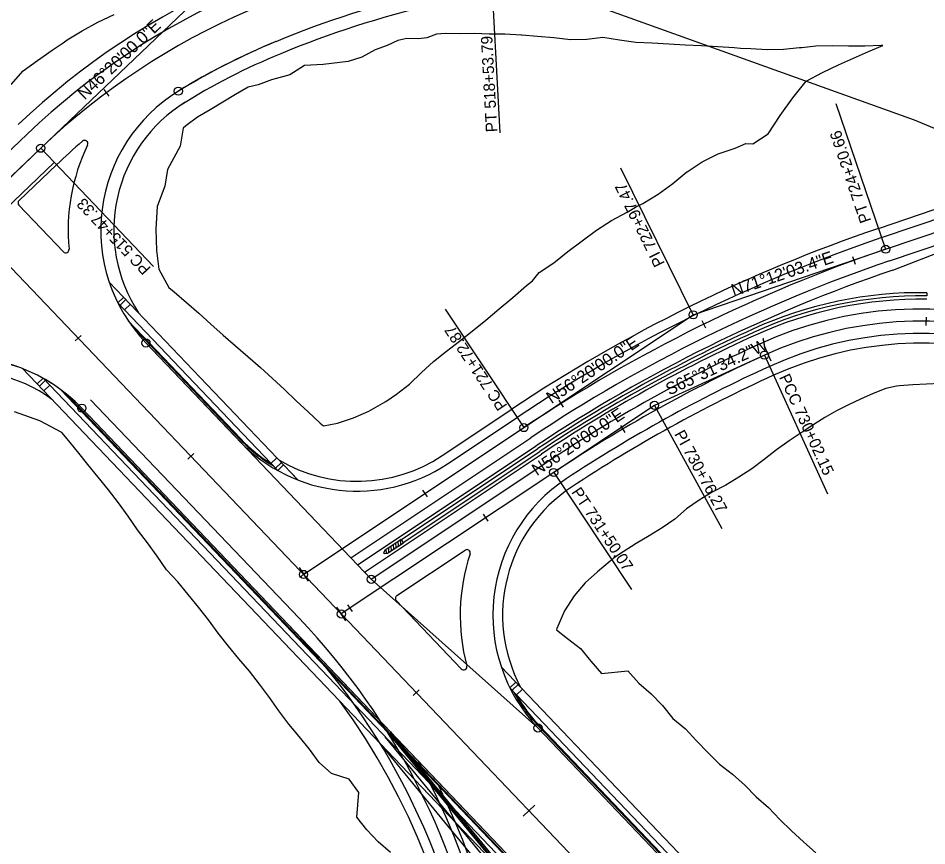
# Model space of a CAD drawing. Extents: x 1300404 to 1323571, y 234004 to 252077.
# Drawn here: x 1310184 to 1310741, y 241283 to 241789 of the extents above; entities that cross this region are included whole.
import ezdxf

# ---------------------------------------------------------------- set-up
doc = ezdxf.new("R2010")
doc.units = 0
for name, color, linetype in [('R_Attenuator', 7, 'Continuous'), ('R_Flooplain', 7, 'Continuous'), ('R_Future', 7, 'Continuous'), ('R_Lane Edge', 7, 'Continuous'), ('R_Shoulder', 7, 'Continuous'), ('R_Sidewalk Edge', 7, 'Continuous'), ('S_CONTOUR_ANNOT', 7, 'Continuous'), ('S_CONTOUR_MINOR', 7, 'Continuous'), ('S_CURB_ANNOT', 7, 'Continuous'), ('S_EDGE_PAVEMENT_ANNOT', 7, 'Continuous'), ('S_ELECTRIC_UTILITIES_ANNOT', 7, 'Continuous'), ('S_LANDSCAPING_ANNOT', 7, 'Continuous'), ('S_POOL', 7, 'Continuous'), ('S_SANITARY_SEWER_ANNOT', 7, 'Continuous'), ('S_SIGN', 7, 'Continuous'), ('S_TREE_ANNOT', 7, 'Continuous'), ('S_UTL_PT_SYM', 7, 'Continuous')]:
    doc.layers.add(name, color=color, linetype=linetype)

msp = doc.modelspace()

# ---------------------------------------------------------------- linework, layer by layer
at = {"layer": 'R_Attenuator'}
for p, q in [((1310412.72, 241463.26), (1310412.54, 241466.14)), ((1310414.16, 241464.22), (1310413.98, 241467.1)), ((1310415.6, 241465.18), (1310415.42, 241468.06)), ((1310417.05, 241466.14), (1310416.86, 241469.03)), ((1310418.49, 241467.1), (1310418.3, 241469.99)), ((1310420.1, 241468.18), (1310418.71, 241470.26)), ((1310419.93, 241468.06), (1310419.9, 241468.47)), ((1310409.02, 241463.8), (1310407.99, 241461.97)), ((1310408.33, 241461.48), (1310408.26, 241462.46)), ((1310408.32, 241461.48), (1310410.41, 241461.72)), ((1310409.82, 241461.65), (1310409.65, 241464.22)), ((1310411.28, 241462.3), (1310411.09, 241465.18))]:
    msp.add_line(p, q, dxfattribs=at)
for points in [[(1310409.02, 241463.8), (1310418.71, 241470.26)], [(1310410.41, 241461.72), (1310420.1, 241468.18)]]:
    msp.add_lwpolyline(points, dxfattribs=at)
msp.add_arc((1310408.49, 241461.95), 0.5, 176.9567, 249.5211, dxfattribs=at)
at = {"layer": 'R_Flooplain'}
msp.add_lwpolyline([(1308850.44, 242983.42), (1308921.9, 242863.68), (1309009.78, 242685.04), (1309044.07, 242596.21), (1309055.9, 242542.38), (1309352.07, 242367.77), (1309503.16, 242292.41), (1309669.46, 242230.8), (1309815.49, 242150.85), (1309936.66, 242057.64), (1310419.39, 241839.75), (1310733.16, 241727.16), (1311043.67, 241597.79), (1311103.17, 241577.86), (1311152.77, 241553.58), (1311178, 241525.7), (1311328.48, 241486.66), (1311553.07, 241380.98), (1311870.34, 241289.99), (1312137.52, 241213.62), (1312460.11, 241035.25)], dxfattribs=at)
at = {"layer": 'R_Future'}
for p, q in [((1310228.47, 241555.74), (1310356.22, 241421.9)), ((1310504.53, 241233.21), (1310408.91, 241349.31)), ((1310506.77, 241235.21), (1310411.16, 241351.31)), ((1310411.52, 241351.65), (1310507.13, 241235.55)), ((1310412.25, 241352.34), (1310507.86, 241236.24)), ((1310500.78, 241229.89), (1310405.17, 241345.99))]:
    msp.add_line(p, q, dxfattribs=at)
for radius, end in [(432.42, 43.6667), (424.92, 43.6667), (418.92, 36.2551), (439.92, 28.6616), (443.92, 26.1864)]:
    msp.add_arc((1310043.42, 241123.33), radius, 336.8233, end, dxfattribs=at)
at = {"layer": 'R_Lane Edge'}
for p, q in [((1310713.17, 241655.01), (1311678.48, 241983.61)), ((1310718.01, 241640.81), (1311683.31, 241969.41)), ((1310165.2, 241695.16), (1310189.58, 241718.44)), ((1310184.6, 241677.73), (1310207.53, 241699.63)), ((1310184.53, 241674.91), (1310211.8, 241646.34)), ((1310262.33, 241590.5), (1310265.86, 241586.81)), ((1310265.86, 241586.81), (1310319.39, 241530.73)), ((1310223.05, 241550.56), (1310370.67, 241395.9)), ((1310447.16, 241516.54), (1310489.78, 241544.93)), ((1310387.84, 241459.01), (1310498.1, 241532.45)), ((1310400.46, 241445.79), (1310508.08, 241517.47)), ((1310416.06, 241435.75), (1310457.92, 241463.64)), ((1310400.46, 241445.79), (1310387.84, 241459.01)), ((1310415.72, 241432.7), (1310455.59, 241390.93)), ((1310370.67, 241395.9), (1310412.25, 241352.34)), ((1310502.57, 241354.75), (1310620.08, 241231.63)), ((1310412.25, 241352.34), (1311200.16, 240526.88))]:
    msp.add_line(p, q, dxfattribs=at)
for centre, radius, start, end in [((1310496.44, 241396.96), 444.42, 93.0604, 133.6667), ((1310574.96, 241212.44), 608.93, 93.92671, 112.49959), ((1310496.44, 241396.96), 408.42, 112.2282, 122.0916), ((1310334.67, 241659.55), 100, 121.6346, 223.6667), ((1310496.44, 241396.96), 418.42, 130.7161, 133.6667), ((1310334.67, 241659.55), 120, 154.2341, 185.5621), ((1310224.8, 241712.58), 2, 334.2336, 130.7163), ((1310185.98, 241676.29), 2, 133.6667, 223.6667), ((1311023.32, 240743.92), 962.43, 108.79905, 123.66667), ((1310213.25, 241647.72), 2, 223.6667, 5.562), ((1311023.32, 240743.92), 947.43, 108.79905, 123.66667), ((1310737.29, 241372.32), 239, 311.1667, 114.4738), ((1310737.29, 241372.32), 224, 311.1667, 114.4738), ((1311023.32, 240743.92), 929.43, 114.47385, 123.66667), ((1310150.71, 241481.51), 100, 43.6667, 147.1828), ((1311023.32, 240743.92), 914.43, 114.47385, 123.40686), ((1310391.73, 241599.77), 100, 223.6667, 303.6667), ((1310574.91, 241423.8), 100, 123.4069, 223.6667), ((1310574.91, 241423.8), 120, 161.7649, 194.9551), ((1310459.03, 241461.97), 2, 341.7649, 123.6667), ((1310417.17, 241434.08), 2, 123.6667, 223.6667), ((1310457.04, 241392.31), 2, 223.6667, 14.9551)]:
    msp.add_arc(centre, radius, start, end, dxfattribs=at)
at = {"layer": 'R_Shoulder'}
for p, q in [((1310711.24, 241660.69), (1311676.55, 241989.29)), ((1310719.94, 241635.13), (1310766.63, 241653.14)), ((1310443.84, 241521.54), (1310486.46, 241549.93)), ((1310392.05, 241454.6), (1310501.42, 241527.45)), ((1310396.26, 241450.2), (1310504.75, 241522.46))]:
    msp.add_line(p, q, dxfattribs=at)
for centre, radius, start, end in [((1310496.44, 241396.96), 452.42, 93.0604, 133.6667), ((1310574.96, 241212.44), 600.93, 93.93245, 112.5014), ((1310496.44, 241396.96), 400.42, 112.2255, 122.0916), ((1310334.67, 241659.55), 92, 121.6346, 213.3062), ((1311023.32, 240743.92), 968.43, 108.79905, 123.66667), ((1311023.32, 240743.92), 941.43, 108.79905, 123.66667), ((1310737.29, 241372.32), 245, 89.1568, 114.4738), ((1311023.32, 240743.92), 935.43, 114.47385, 123.66667), ((1310737.29, 241372.32), 218, 311.1667, 114.4738), ((1310150.71, 241481.51), 92, 54.0272, 147.1828), ((1311023.32, 240743.92), 908.43, 114.47385, 123.40686), ((1310391.73, 241599.77), 94, 239.3509, 303.6667), ((1310574.91, 241423.8), 94, 123.4069, 207.9824)]:
    msp.add_arc(centre, radius, start, end, dxfattribs=at)
at = {"layer": 'R_Sidewalk Edge'}
for p, q in [((1310239.83, 241627.83), (1310355.64, 241506.51)), ((1310248.73, 241618.52), (1310245.11, 241615.06)), ((1310250.11, 241617.07), (1310246.49, 241613.62)), ((1310245.11, 241615.06), (1310343.13, 241512.38)), ((1310252.87, 241614.18), (1310249.25, 241610.72)), ((1310186.8, 241574.77), (1310385.11, 241367.02)), ((1310199.31, 241568.91), (1310195.69, 241565.45)), ((1310200.69, 241567.46), (1310197.07, 241564.01)), ((1310199.31, 241568.91), (1310378.2, 241381.49)), ((1310203.45, 241564.57), (1310199.84, 241561.11)), ((1310338.98, 241516.72), (1310342.6, 241520.17)), ((1310341.75, 241513.82), (1310345.36, 241517.28)), ((1310343.13, 241512.38), (1310346.74, 241515.83)), ((1310349.8, 241512.62), (1310355.64, 241506.51)), ((1310480.07, 241392.08), (1310628.7, 241236.37)), ((1310488.96, 241382.76), (1310485.35, 241379.31)), ((1310378.2, 241381.49), (1310655.54, 241090.93)), ((1310485.35, 241379.31), (1310624.89, 241233.12)), ((1310490.34, 241381.32), (1310486.73, 241377.86)), ((1310493.11, 241378.42), (1310489.49, 241374.97)), ((1310385.11, 241367.02), (1310651.77, 241087.64))]:
    msp.add_line(p, q, dxfattribs=at)
at = {"layer": 'S_CONTOUR_ANNOT'}
for p, q in [((1310197.87, 241709.76), (1310313.6, 241820.22)), ((1310597.64, 241607.76), (1310715.59, 241647.91)), ((1310493.94, 241538.69), (1310597.64, 241607.76)), ((1310641.38, 241583.02), (1310573.92, 241552.31)), ((1310573.92, 241552.31), (1310512.23, 241511.22))]:
    msp.add_line(p, q, dxfattribs=at)
at = {"layer": 'S_CURB_ANNOT'}
for p, q in [((1310740.8, 241621.29), (1310740.77, 241619.29)), ((1310418.85, 241470.05), (1310502.53, 241525.79)), ((1310419.96, 241468.38), (1310503.64, 241524.12)), ((1310419.96, 241468.38), (1310418.85, 241470.05))]:
    msp.add_line(p, q, dxfattribs=at)
for centre, radius, start, end in [((1310737.29, 241372.32), 249, 89.1924, 114.4738), ((1310737.29, 241372.32), 247, 89.1924, 114.4738), ((1311023.32, 240743.92), 939.43, 114.47385, 123.66667), ((1311023.32, 240743.92), 937.43, 114.47385, 123.66667)]:
    msp.add_arc(centre, radius, start, end, dxfattribs=at)
at = {"layer": 'S_EDGE_PAVEMENT_ANNOT'}
for points in [[(1310473.35, 241828.76), (1310479.21, 241719.2)], [(1310685.18, 241737.26), (1310715.59, 241647.91)], [(1310197.87, 241709.76), (1310266.91, 241637.42)], [(1310597.64, 241607.76), (1310553.44, 241697.46)], [(1310445.66, 241611.18), (1310493.94, 241538.69)], [(1310641.38, 241583.02), (1310680.08, 241498.01)], [(1310573.92, 241552.31), (1310615.3, 241476.78)], [(1310512.23, 241511.22), (1310559.98, 241439.54)]]:
    msp.add_lwpolyline(points, dxfattribs=at)
at = {"layer": 'S_ELECTRIC_UTILITIES_ANNOT'}
for points in [[(1310179.85, 241748.72), (1310187.06, 241757.12), (1310195.99, 241763.55), (1310204.95, 241769.88), (1310211.59, 241774.39), (1310214, 241776.06), (1310223.37, 241781.73), (1310232.94, 241787.06), (1310242.9, 241791.7)], [(1310713.95, 241772.69), (1310712.9, 241772.72), (1310702.91, 241772.17), (1310692.89, 241772.34), (1310682.87, 241772.5), (1310672.87, 241772.24), (1310664.19, 241771.34), (1310662.91, 241771.2), (1310652.95, 241770.15), (1310642.95, 241769.98), (1310632.9, 241770.57), (1310626.66, 241770.88), (1310622.85, 241771.17), (1310612.8, 241771.81), (1310602.76, 241772.39), (1310592.71, 241772.96), (1310582.67, 241773.5), (1310572.63, 241774.03), (1310562.59, 241774.57), (1310552.5, 241775.86), (1310542.4, 241777.49), (1310532.44, 241776.42), (1310522.44, 241776.25), (1310512.36, 241777.44), (1310502.3, 241778.22), (1310492.71, 241778.96), (1310492.25, 241778.99), (1310482.2, 241779.56), (1310472.62, 241779.54), (1310463.69, 241779.93), (1310454.75, 241779.92), (1310445.76, 241779.98), (1310440.44, 241779.54), (1310434.56, 241777.46), (1310429.44, 241776.71), (1310422.15, 241776.9), (1310416.67, 241775.82), (1310410.07, 241772.76), (1310402.81, 241770.07), (1310394.62, 241765.57), (1310386.34, 241762.93), (1310370.98, 241760.99), (1310359.58, 241760.38), (1310350.48, 241754.73), (1310339.31, 241751.73), (1310331.18, 241748.58), (1310324.96, 241747.19), (1310317.19, 241742.58), (1310309.49, 241737.9), (1310301.79, 241733.25), (1310294.04, 241728.7), (1310286.73, 241723.46), (1310285.06, 241721.97), (1310283.4, 241710.95), (1310275.56, 241696.75), (1310273.87, 241686.49)], [(1310371.07, 241539.73), (1310379.67, 241541.4), (1310389.57, 241544.57), (1310398.83, 241548.72), (1310407.51, 241553.71), (1310409.3, 241554.76), (1310415.87, 241559.2), (1310423.84, 241565.27), (1310431.11, 241572.41), (1310438.62, 241579.17), (1310446.46, 241585.44), (1310454.39, 241591.57), (1310462.29, 241597.75), (1310470.64, 241604.43), (1310478.88, 241611.49), (1310487.25, 241618.41), (1310495.48, 241625.62), (1310499.13, 241628.6), (1310503.28, 241633.64), (1310512.36, 241639.56), (1310520.92, 241646.43), (1310529.71, 241652.96), (1310538.52, 241659.52), (1310547.68, 241665.47), (1310557.31, 241670.56), (1310562.39, 241673.58), (1310566.78, 241675.98), (1310576.13, 241681.68), (1310585.11, 241688.21), (1310593.88, 241695.29), (1310593.96, 241695.36), (1310603.1, 241701.51), (1310612.99, 241706.29), (1310623.39, 241709.9), (1310629.93, 241712.74), (1310634.18, 241712.5), (1310643.57, 241718.54), (1310650.98, 241729.81), (1310658.72, 241740.66), (1310666.89, 241750.78), (1310676.89, 241756.13), (1310686.82, 241760.86), (1310696.01, 241764.91), (1310705.2, 241768.92), (1310713.95, 241772.69)], [(1310273.87, 241686.49), (1310269.18, 241674.17), (1310268.49, 241660.3), (1310268.85, 241647.05), (1310270.15, 241635.61), (1310276.3, 241624.5), (1310279.63, 241621.91), (1310287.24, 241615.34), (1310294.73, 241608.67), (1310302.19, 241601.97), (1310309.72, 241595.33), (1310317.28, 241588.72), (1310324.88, 241582.15), (1310332.48, 241575.58), (1310339.88, 241568.83), (1310347.18, 241561.97), (1310354.48, 241555.11), (1310361.76, 241548.24), (1310369.18, 241541.49), (1310371.07, 241539.73)], [(1310749.04, 241565.61), (1310740.68, 241565.33), (1310732.34, 241564.89), (1310724.02, 241564.21), (1310722.19, 241564.03), (1310715.82, 241562.65), (1310707.94, 241559.54), (1310700.28, 241556.09), (1310692.75, 241552.7), (1310685.45, 241548.96), (1310678.42, 241544.83), (1310671.6, 241540.5), (1310664.55, 241535.88), (1310656.58, 241530.6), (1310648.79, 241525.04), (1310641.19, 241519.19), (1310633.6, 241513.39), (1310625.69, 241508.26), (1310617.59, 241503.52), (1310609.3, 241499.14), (1310601.25, 241494.32), (1310593.6, 241488.84), (1310586.42, 241482.62), (1310578.74, 241477.27), (1310570.71, 241472.49), (1310562.69, 241467.68), (1310554.82, 241462.63), (1310548.88, 241458.65), (1310546.71, 241456.87), (1310539.06, 241450.31), (1310531.47, 241443.67), (1310524.82, 241435.62), (1310518.85, 241426.54), (1310514.16, 241415.54), (1310513.92, 241414.84)], [(1310412.25, 241278.47), (1310404.66, 241285.05), (1310397.74, 241292.27), (1310391.55, 241300.19), (1310392.84, 241315.24), (1310386.9, 241323.4), (1310376.08, 241326.89), (1310368.52, 241333.5), (1310362.56, 241341.64), (1310356.32, 241349.5), (1310349.83, 241357.13), (1310343.87, 241365.27), (1310337.99, 241373.48), (1310331.94, 241381.53), (1310325.71, 241389.41), (1310319.31, 241397.12), (1310312.94, 241404.87), (1310306.65, 241412.69), (1310300.74, 241420.87), (1310294.46, 241428.7), (1310288.14, 241436.49), (1310281.82, 241444.28), (1310274.89, 241451.5), (1310269.22, 241459.9), (1310263.24, 241468.02), (1310257.25, 241476.13), (1310251.47, 241484.43), (1310245.49, 241492.55), (1310239.39, 241500.55), (1310233.1, 241508.38), (1310226.79, 241516.17), (1310220.44, 241523.94), (1310214.15, 241531.76), (1310210.9, 241535.73), (1310197.32, 241542.9), (1310181.81, 241548.26)], [(1310513.92, 241414.84), (1310520.57, 241409.52), (1310528.62, 241403.37), (1310534.9, 241395.54), (1310541.5, 241388.02), (1310557.7, 241389.66), (1310564.32, 241382.15), (1310571.9, 241375.56), (1310578.95, 241368.47), (1310585.18, 241360.59), (1310592.91, 241354.15), (1310599.69, 241346.79), (1310606.7, 241339.66), (1310613.76, 241332.58), (1310621.79, 241326.42), (1310629.24, 241319.7), (1310636.31, 241312.62), (1310643.79, 241305.93), (1310650.76, 241298.76), (1310657.86, 241291.73), (1310665.31, 241285), (1310672.81, 241278.34)]]:
    msp.add_lwpolyline(points, dxfattribs=at)
at = {"layer": 'S_LANDSCAPING_ANNOT'}
for p, q in [((1310715.59, 241647.91), (1311680.9, 241976.51)), ((1310111.34, 241627.16), (1310197.87, 241709.76)), ((1310111.34, 241627.16), (1310197.87, 241709.76)), ((1310111.34, 241627.16), (1310197.87, 241709.76)), ((1310151.78, 241665.77), (1310197.87, 241709.76)), ((1310151.78, 241665.77), (1311952.58, 239779.15)), ((1310165.59, 241651.3), (1311952.63, 239779.09)), ((1310165.59, 241651.3), (1311952.63, 239779.09)), ((1310262.33, 241590.5), (1310400.46, 241445.79)), ((1310223.05, 241550.56), (1311374.36, 240344.37)), ((1310358.92, 241448.76), (1310493.94, 241538.69)), ((1310512.23, 241511.22), (1310382.06, 241424.52)), ((1310400.46, 241445.79), (1310502.57, 241354.75)), ((1310502.57, 241354.75), (1310620.08, 241231.63))]:
    msp.add_line(p, q, dxfattribs=at)
for centre in [(1310282.22, 241744.69), (1310197.87, 241709.76), (1310715.59, 241647.91), (1310597.64, 241607.76), (1310262.33, 241590.5), (1310641.38, 241583.02), (1310223.05, 241550.56), (1310573.92, 241552.31), (1310493.94, 241538.69), (1310512.23, 241511.22), (1310358.92, 241448.76), (1310400.46, 241445.79), (1310382.06, 241424.52), (1310502.57, 241354.75)]:
    msp.add_circle(centre, 2.5, dxfattribs=at)
for centre, radius, start, end in [((1310496.44, 241396.96), 432.42, 93.0604, 133.6667), ((1310334.67, 241659.55), 100, 121.6346, 223.6667), ((1311023.32, 240743.92), 954.93, 108.79905, 123.66667), ((1310737.29, 241372.32), 231.5, 311.1667, 114.4738), ((1311023.32, 240743.92), 921.93, 114.47385, 123.66667), ((1310150.71, 241481.51), 100, 43.6667, 147.1828)]:
    msp.add_arc(centre, radius, start, end, dxfattribs=at)
at = {"layer": 'S_POOL'}
msp.add_line((1310119.62, 241618.48), (1310206.15, 241701.08), dxfattribs=at)
for centre, radius, start, end in [((1310574.96, 241212.44), 608.93, 93.92671, 112.49959), ((1310496.44, 241396.96), 408.42, 112.2282, 121.6346), ((1310334.67, 241659.55), 100, 121.6346, 223.6667), ((1310150.71, 241481.51), 100, 43.6667, 147.1004)]:
    msp.add_arc(centre, radius, start, end, dxfattribs=at)
at = {"layer": 'S_SANITARY_SEWER_ANNOT'}
for points in [[(1310645.37, 241579.33), (1310641.31, 241588.47)], [(1310356.15, 241452.92), (1310361.7, 241444.6)], [(1310356.15, 241452.92), (1310361.7, 241444.6)], [(1310384.83, 241420.36), (1310379.29, 241428.68)], [(1310500.63, 241307.54), (1310493.4, 241300.63)]]:
    msp.add_lwpolyline(points, dxfattribs=at)
at = {"layer": 'S_SIGN'}
for points in [[(1310236.6, 241745.72), (1310239.58, 241741.71)], [(1310695.24, 241643.39), (1310696.95, 241638.69)], [(1310740.51, 241601.3), (1310740.58, 241606.3)], [(1310603.02, 241604.17), (1310605.21, 241599.68)], [(1310222.64, 241595.16), (1310219.02, 241591.71)], [(1310515.4, 241555.52), (1310518.05, 241551.28)], [(1310555.91, 241535.68), (1310553.37, 241539.99)], [(1310291.69, 241522.82), (1310288.07, 241519.37)], [(1310431.9, 241500.37), (1310434.67, 241496.21)], [(1310472.06, 241481.46), (1310469.29, 241485.62)], [(1310360.73, 241450.48), (1310357.11, 241447.03)], [(1310388.83, 241426.03), (1310386.06, 241430.19)], [(1310429.78, 241378.15), (1310426.16, 241374.69)]]:
    msp.add_lwpolyline(points, dxfattribs=at)
at = {"layer": 'S_TREE_ANNOT'}
for p, q in [((1310251.51, 241604.02), (1310320.48, 241531.76)), ((1310253.32, 241601.4), (1310320.11, 241531.42)), ((1310210.05, 241562), (1310373.35, 241390.92)), ((1310212.58, 241560.07), (1310372.48, 241392.56)), ((1310372.48, 241392.56), (1310671.99, 241078.77)), ((1310373.35, 241390.92), (1310671.61, 241078.44)), ((1310503.29, 241355.44), (1310622.23, 241230.84)), ((1310503.65, 241355.78), (1310622.61, 241231.16))]:
    msp.add_line(p, q, dxfattribs=at)
for centre, radius, start, end in [((1310391.73, 241599.77), 99, 223.6667, 238.9473), ((1310391.73, 241599.77), 98.5, 223.6667, 237.8438), ((1310574.91, 241423.8), 99, 208.386, 223.6667), ((1310574.91, 241423.8), 98.5, 209.4895, 223.6667)]:
    msp.add_arc(centre, radius, start, end, dxfattribs=at)

# ---------------------------------------------------------------- texts
at = {"layer": 'S_CONTOUR_MINOR'}
for s, rotation, p in [('N46%%d20\'00.0"E', 43.6667, (1310224.83, 241738.95)), ('N71%%d12\'03.4"E', 18.7991, (1310622.51, 241618.87)), ('N56%%d20\'00.0"E', 33.6667, (1310510.84, 241552.95)), ('S65%%d31\'34.2"W', 25.0467, (1310583.03, 241558.26)), ('N56%%d20\'00.0"E', 33.6667, (1310501.94, 241508.87))]:
    msp.add_text(s, height=7.5, rotation=rotation, dxfattribs=at).set_placement(p)
at = {"layer": 'S_UTL_PT_SYM'}
for s, rotation, p in [('PT 518+53.79', 93.0604, (1310477.68, 241719.76)), ('PT 724+20.66', 108.7991, (1310706.86, 241665.38)), ('PI 722+97.47', 116.2329, (1310580.47, 241639.21)), ('PC 515+47.33', 133.6667, (1310265.83, 241636.38)), ('PC 721+72.87', 123.6667, (1310484.04, 241552.09)), ('PCC 730+02.15', 294.4738, (1310650.16, 241569.58)), ('PI 730+76.27', 298.7136, (1310585.92, 241534.75)), ('PT 731+50.07', 303.6667, (1310522.79, 241499.15))]:
    msp.add_text(s, height=7, rotation=rotation, dxfattribs=at).set_placement(p)

doc.saveas('drawing.dxf')
